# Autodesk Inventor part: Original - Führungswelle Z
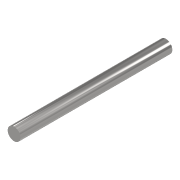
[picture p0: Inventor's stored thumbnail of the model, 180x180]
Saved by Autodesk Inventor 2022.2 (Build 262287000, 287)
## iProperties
Created: 2024-09
Part Number: Original - Führungswelle Z
Material: Acciaio inossidabile
Document SubType Name: Modeling
Designer: 18907419
Density: 8 g/cm^3
Appearance: Acciaio - Lucido
Author: 18907419
Revision Number: ANY
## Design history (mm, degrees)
feature "Aufsatz-Linear austragen1"
node "Solido1"
